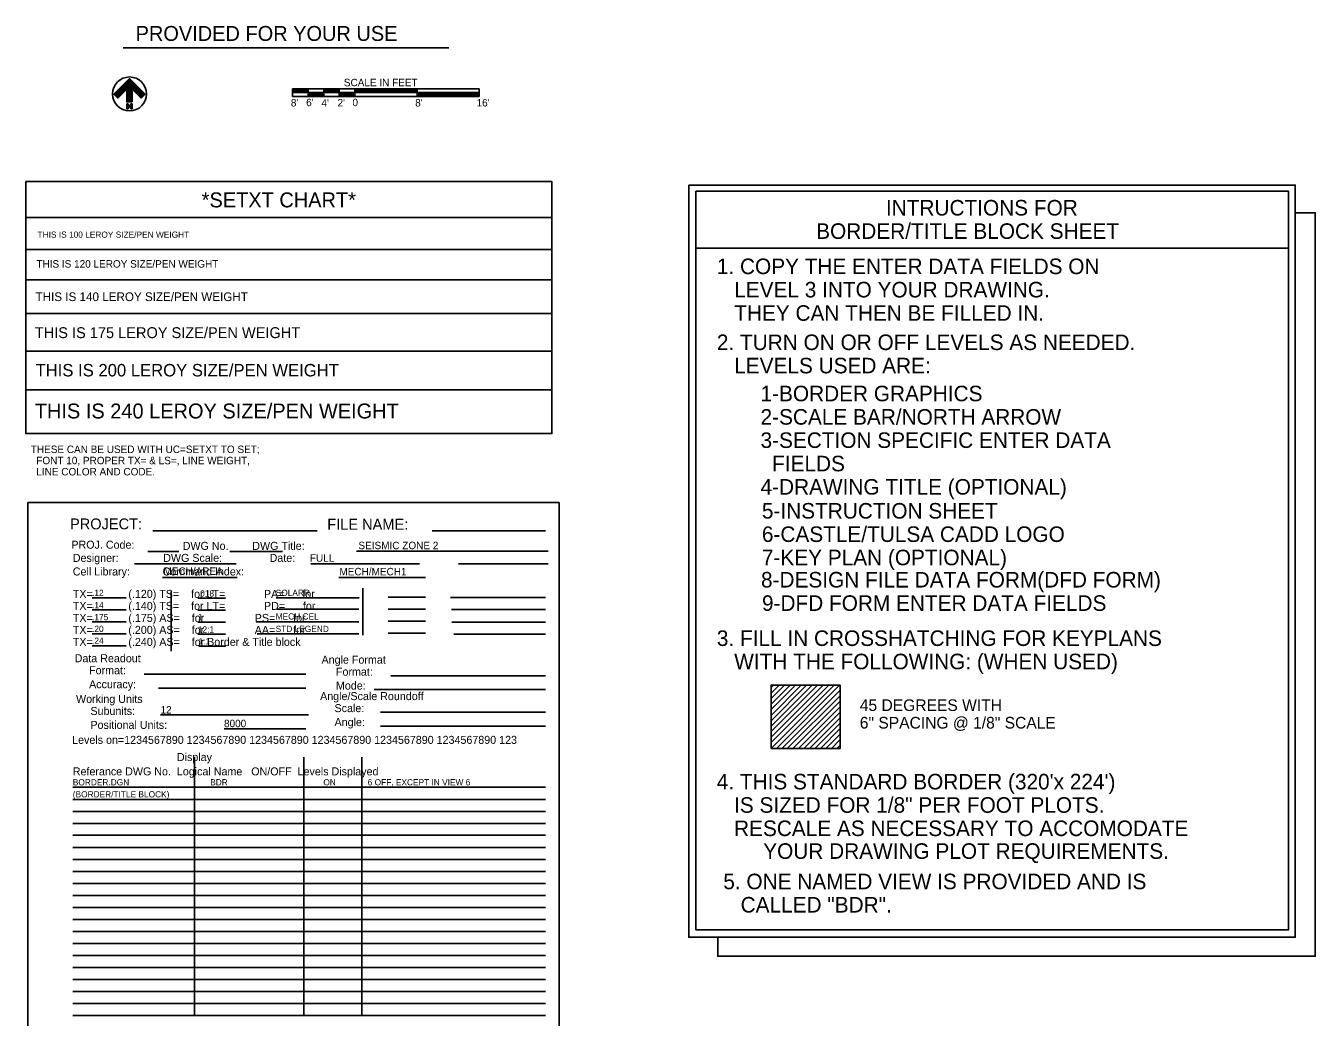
# Model space of a CAD drawing. Extents: x 9999.96 to 10005.26, y 9999.88 to 10002.38.
# Drawn here: x 10003.531 to 10005.258, y 10001.056 to 10002.384 of the extents above; entities that cross this region are included whole.
import ezdxf

# ---------------------------------------------------------------- set-up
doc = ezdxf.new("R2010")
doc.units = 0
for name, color, linetype in [('Level 2', 7, 'Continuous'), ('Level 5', 7, 'Continuous'), ('Level 8', 7, 'Continuous'), ('Level 9', 7, 'Continuous')]:
    doc.layers.add(name, color=color, linetype=linetype)

msp = doc.modelspace()

# ---------------------------------------------------------------- linework, layer by layer
at = {"layer": 'Level 2'}
for p, q in [((10003.6703, 10002.2818), (10003.6703, 10002.3131)), ((10003.8886, 10002.2995), (10004.1386, 10002.2995)), ((10003.8886, 10002.2995), (10003.8886, 10002.2891)), ((10003.8886, 10002.299), (10003.9095, 10002.299)), ((10003.8886, 10002.2981), (10003.9095, 10002.2981)), ((10003.8886, 10002.2973), (10003.9095, 10002.2973)), ((10003.8886, 10002.2964), (10003.9095, 10002.2964)), ((10003.8886, 10002.2955), (10003.9095, 10002.2955)), ((10003.8886, 10002.2947), (10003.9095, 10002.2947)), ((10003.9095, 10002.2995), (10003.9095, 10002.2891)), ((10003.9303, 10002.2995), (10003.9303, 10002.2891)), ((10003.9303, 10002.299), (10003.9511, 10002.299)), ((10003.9303, 10002.2981), (10003.9511, 10002.2981)), ((10003.9303, 10002.2972), (10003.9511, 10002.2972)), ((10003.9303, 10002.2964), (10003.9511, 10002.2964)), ((10003.9303, 10002.2955), (10003.9511, 10002.2955)), ((10003.9303, 10002.2946), (10003.9511, 10002.2946)), ((10003.9511, 10002.2995), (10003.9511, 10002.2891)), ((10003.9719, 10002.2989), (10004.0553, 10002.2989)), ((10003.9719, 10002.298), (10004.0553, 10002.298)), ((10003.9719, 10002.2971), (10004.0553, 10002.2971)), ((10003.9719, 10002.2963), (10004.0553, 10002.2963)), ((10003.9719, 10002.2954), (10004.0553, 10002.2954)), ((10003.972, 10002.2995), (10003.972, 10002.2891)), ((10004.0553, 10002.2995), (10004.0553, 10002.2891)), ((10004.1386, 10002.2995), (10004.1386, 10002.2891)), ((10003.6674, 10002.2726), (10003.6674, 10002.2792)), ((10003.6679, 10002.2726), (10003.6679, 10002.2792)), ((10003.6679, 10002.2788), (10003.6726, 10002.273)), ((10003.6726, 10002.2726), (10003.6726, 10002.2792)), ((10003.6731, 10002.2726), (10003.6731, 10002.2792)), ((10003.8886, 10002.2943), (10004.1386, 10002.2943)), ((10003.8886, 10002.2891), (10004.1386, 10002.2891)), ((10003.9094, 10002.2939), (10003.9303, 10002.2939)), ((10003.9094, 10002.293), (10003.9303, 10002.293)), ((10003.9094, 10002.2921), (10003.9303, 10002.2921)), ((10003.9094, 10002.2913), (10003.9303, 10002.2913)), ((10003.9094, 10002.2904), (10003.9303, 10002.2904)), ((10003.9094, 10002.2895), (10003.9303, 10002.2895)), ((10003.9511, 10002.2939), (10003.9719, 10002.2939)), ((10003.9511, 10002.293), (10003.9719, 10002.293)), ((10003.9511, 10002.2921), (10003.9719, 10002.2921)), ((10003.9511, 10002.2913), (10003.9719, 10002.2913)), ((10003.9511, 10002.2904), (10003.9719, 10002.2904)), ((10003.9511, 10002.2895), (10003.9719, 10002.2895)), ((10004.0553, 10002.2935), (10004.1386, 10002.2935)), ((10004.0553, 10002.2926), (10004.1386, 10002.2926)), ((10004.0553, 10002.2918), (10004.1386, 10002.2918)), ((10004.0553, 10002.2909), (10004.1386, 10002.2909)), ((10004.0553, 10002.29), (10004.1386, 10002.29))]:
    msp.add_line(p, q, dxfattribs=at)
for points in [[(10003.6739, 10002.2818), (10003.6739, 10002.299), (10003.6859, 10002.287), (10003.6911, 10002.2923), (10003.6703, 10002.3131), (10003.6494, 10002.2923), (10003.6546, 10002.287), (10003.6666, 10002.299), (10003.6666, 10002.2818)], [(10003.6668, 10002.2726), (10003.6668, 10002.2792), (10003.6682, 10002.2792), (10003.672, 10002.2744), (10003.672, 10002.2792), (10003.6737, 10002.2792), (10003.6737, 10002.2726), (10003.6723, 10002.2726), (10003.6685, 10002.2774), (10003.6685, 10002.2726)]]:
    msp.add_lwpolyline(points, close=True, dxfattribs=at)
for points in [[(10003.6501, 10002.2916), (10003.6703, 10002.3118), (10003.6904, 10002.2916)], [(10003.6507, 10002.291), (10003.6703, 10002.3105), (10003.6898, 10002.291)], [(10003.6514, 10002.2903), (10003.6703, 10002.3092), (10003.6891, 10002.2903)], [(10003.652, 10002.2897), (10003.6703, 10002.3079), (10003.6885, 10002.2897)], [(10003.6693, 10002.2818), (10003.6693, 10002.3057), (10003.6527, 10002.289)], [(10003.6684, 10002.2818), (10003.6684, 10002.3034), (10003.6533, 10002.2884)], [(10003.6675, 10002.2818), (10003.6675, 10002.3012), (10003.654, 10002.2877)], [(10003.6666, 10002.2818), (10003.6666, 10002.299), (10003.6546, 10002.287)], [(10003.6712, 10002.2818), (10003.6712, 10002.3057), (10003.6878, 10002.289)], [(10003.6721, 10002.2818), (10003.6721, 10002.3034), (10003.6872, 10002.2884)], [(10003.673, 10002.2818), (10003.673, 10002.3012), (10003.6865, 10002.2877)]]:
    msp.add_lwpolyline(points, dxfattribs=at)
msp.add_circle((10003.6703, 10002.2925), 0.0227, dxfattribs=at)
at = {"layer": 'Level 5'}
for p, q in [((10003.6616, 10002.3543), (10004.0978, 10002.3543)), ((10003.5313, 10002.127), (10004.2359, 10002.127)), ((10003.5313, 10002.0844), (10004.2359, 10002.0844)), ((10004.4285, 10002.0859), (10005.2225, 10002.0859)), ((10003.5313, 10002.0437), (10004.2359, 10002.0437)), ((10003.5313, 10001.9983), (10004.2359, 10001.9983)), ((10003.5313, 10001.9482), (10004.2359, 10001.9482)), ((10003.5313, 10001.8962), (10004.2359, 10001.8962)), ((10004.5291, 10001.4749), (10004.5549, 10001.5006)), ((10004.5291, 10001.4527), (10004.5769, 10001.5005)), ((10004.5291, 10001.4233), (10004.6063, 10001.5004)), ((10004.5291, 10001.4306), (10004.5989, 10001.5004)), ((10004.5292, 10001.4971), (10004.5328, 10001.5006)), ((10004.5292, 10001.4676), (10004.5622, 10001.5005)), ((10004.5292, 10001.4897), (10004.54, 10001.5005)), ((10004.5293, 10001.4161), (10004.6138, 10001.5006)), ((10004.5293, 10001.4603), (10004.5696, 10001.5006)), ((10004.5293, 10001.4456), (10004.5843, 10001.5005)), ((10004.5365, 10001.4159), (10004.6211, 10001.5006)), ((10004.5291, 10001.4822), (10004.5471, 10001.5002)), ((10004.5292, 10001.4381), (10004.5913, 10001.5002)), ((10004.5439, 10001.4159), (10004.622, 10001.4941)), ((10004.5516, 10001.4163), (10004.6219, 10001.4866)), ((10004.5588, 10001.4162), (10004.6219, 10001.4793)), ((10004.5661, 10001.4161), (10004.6218, 10001.4718)), ((10004.5734, 10001.4161), (10004.6219, 10001.4645)), ((10004.5808, 10001.416), (10004.6218, 10001.4571)), ((10004.5881, 10001.416), (10004.6221, 10001.45)), ((10004.5955, 10001.416), (10004.6219, 10001.4425)), ((10004.6027, 10001.4158), (10004.6221, 10001.4352)), ((10004.6103, 10001.4161), (10004.6221, 10001.4278)), ((10004.6176, 10001.4161), (10004.6221, 10001.4205))]:
    msp.add_line(p, q, dxfattribs=at)
for points in [[(10003.5313, 10002.1752), (10004.2359, 10002.1752), (10004.2359, 10001.8376), (10003.5313, 10001.8376), (10003.5313, 10002.1752)], [(10004.4192, 10002.1705), (10005.2314, 10002.1705), (10005.2314, 10001.1631), (10004.4192, 10001.1631), (10004.4192, 10002.1705)], [(10004.4285, 10002.1621), (10005.2225, 10002.1621), (10005.2225, 10001.1732), (10004.4285, 10001.1732), (10004.4285, 10002.1621)], [(10005.2314, 10002.1335), (10005.2581, 10002.1335), (10005.2581, 10001.1376), (10004.4579, 10001.1376), (10004.4579, 10001.1631)]]:
    msp.add_lwpolyline(points, dxfattribs=at)
msp.add_lwpolyline([(10004.5293, 10001.4161), (10004.5293, 10001.5006), (10004.6221, 10001.5006), (10004.6221, 10001.4161)], close=True, dxfattribs=at)
at = {"layer": 'Level 8'}
for p, q in [((10003.5343, 9999.912), (10003.5343, 10001.7453)), ((10003.5343, 10001.7453), (10004.2454, 10001.7453)), ((10004.2454, 10001.7453), (10004.2454, 9999.912)), ((10003.9217, 10001.7073), (10003.7016, 10001.7073)), ((10004.2274, 10001.7073), (10004.0755, 10001.7073)), ((10003.7361, 10001.6795), (10003.6947, 10001.6795)), ((10003.8753, 10001.6795), (10003.8045, 10001.6795)), ((10004.231, 10001.6801), (10003.9744, 10001.6801)), ((10003.6768, 10001.6632), (10003.8132, 10001.6632)), ((10003.9129, 10001.6632), (10004.0588, 10001.6632)), ((10004.1108, 10001.6632), (10004.231, 10001.6632)), ((10003.7145, 10001.645), (10003.8143, 10001.645)), ((10003.9507, 10001.645), (10004.0665, 10001.645)), ((10003.7261, 10001.6262), (10003.7261, 10001.5464)), ((10003.9829, 10001.5676), (10003.9829, 10001.6304)), ((10003.6658, 10001.6176), (10003.6204, 10001.6176)), ((10003.7989, 10001.6171), (10003.7619, 10001.6171)), ((10003.9778, 10001.6178), (10003.8665, 10001.6178)), ((10004.0665, 10001.6185), (10004.0167, 10001.6185)), ((10004.2274, 10001.6179), (10004.1003, 10001.6179)), ((10003.6658, 10001.6015), (10003.6204, 10001.6015)), ((10003.7989, 10001.6011), (10003.7619, 10001.6011)), ((10003.9772, 10001.6023), (10003.8676, 10001.6023)), ((10004.0665, 10001.6024), (10004.0167, 10001.6024)), ((10004.2274, 10001.6019), (10004.1014, 10001.6019)), ((10003.6658, 10001.5854), (10003.6204, 10001.5854)), ((10003.7989, 10001.585), (10003.7619, 10001.585)), ((10003.9772, 10001.5857), (10003.84, 10001.5857)), ((10003.9772, 10001.5696), (10003.841, 10001.5696)), ((10004.0665, 10001.5863), (10004.0167, 10001.5863)), ((10004.0665, 10001.5703), (10004.0167, 10001.5703)), ((10004.2274, 10001.5853), (10004.1019, 10001.5853)), ((10003.6658, 10001.5694), (10003.6204, 10001.5694)), ((10003.6658, 10001.5533), (10003.6204, 10001.5533)), ((10003.7989, 10001.5689), (10003.7619, 10001.5689)), ((10003.7989, 10001.5528), (10003.763, 10001.5528)), ((10004.2274, 10001.5692), (10004.1047, 10001.5692)), ((10003.9064, 10001.5153), (10003.6897, 10001.5153)), ((10004.02, 10001.5134), (10004.2274, 10001.5134)), ((10003.9064, 10001.4966), (10003.7092, 10001.4966)), ((10004.2274, 10001.4948), (10003.9979, 10001.4948)), ((10003.91, 10001.4608), (10003.7118, 10001.4608)), ((10004.2274, 10001.4646), (10004.0063, 10001.4646)), ((10003.9064, 10001.4422), (10003.797, 10001.4422)), ((10004.2274, 10001.4459), (10004.0063, 10001.4459)), ((10003.7574, 10001.4044), (10003.7574, 10001.0584)), ((10003.9037, 10001.4044), (10003.9037, 10001.0595)), ((10003.9814, 10001.4044), (10003.9814, 10001.0584)), ((10004.2274, 10001.3639), (10003.5943, 10001.3639)), ((10004.2274, 10001.3478), (10003.5943, 10001.3478)), ((10004.2274, 10001.3317), (10003.5943, 10001.3317)), ((10004.2274, 10001.3156), (10003.5943, 10001.3156)), ((10004.2274, 10001.2996), (10003.5943, 10001.2996)), ((10004.2274, 10001.2835), (10003.5943, 10001.2835)), ((10004.2274, 10001.2674), (10003.5943, 10001.2674)), ((10004.2274, 10001.2513), (10003.5943, 10001.2513)), ((10004.2274, 10001.2352), (10003.5943, 10001.2352)), ((10004.2274, 10001.2192), (10003.5943, 10001.2192)), ((10004.2274, 10001.2031), (10003.5943, 10001.2031)), ((10004.2274, 10001.187), (10003.5943, 10001.187)), ((10004.2274, 10001.1709), (10003.5943, 10001.1709)), ((10004.2274, 10001.1549), (10003.5943, 10001.1549)), ((10004.2274, 10001.1388), (10003.5943, 10001.1388)), ((10004.2274, 10001.1227), (10003.5943, 10001.1227)), ((10004.2274, 10001.1066), (10003.5943, 10001.1066)), ((10004.2274, 10001.0906), (10003.5943, 10001.0906)), ((10004.2274, 10001.0745), (10003.5943, 10001.0745)), ((10004.2274, 10001.0584), (10003.5943, 10001.0584))]:
    msp.add_line(p, q, dxfattribs=at)

# ---------------------------------------------------------------- texts
at = {"layer": 'Level 2'}
for s, p in [('SCALE IN FEET', (10003.9573, 10002.3028)), ("8'", (10003.8863, 10002.2757)), ("6'", (10003.9068, 10002.2761)), ("4'", (10003.9272, 10002.2754)), ("2'", (10003.9488, 10002.2757)), ('0', (10003.9688, 10002.2761)), ("8'", (10004.0528, 10002.2757)), ("16'", (10004.135, 10002.2757))]:
    msp.add_text(s, height=0.01, dxfattribs=at).set_placement(p)
at = {"layer": 'Level 5'}
for s, height, p in [('PROVIDED FOR YOUR USE', 0.02, (10003.6784, 10002.3635)), ('*SETXT CHART*', 0.02, (10003.7669, 10002.1406)), ('INTRUCTIONS FOR', 0.020833, (10004.6832, 10002.1297)), ('THIS IS 100 LEROY SIZE/PEN WEIGHT', 0.008333, (10003.5471, 10002.0999)), ('BORDER/TITLE BLOCK SHEET', 0.020833, (10004.5898, 10002.0984)), ('THIS IS 120 LEROY SIZE/PEN WEIGHT', 0.01, (10003.5455, 10002.0599)), ('1. COPY THE ENTER DATA FIELDS ON', 0.020833, (10004.4568, 10002.0512)), ('   LEVEL 3 INTO YOUR DRAWING.', 0.020833, (10004.4568, 10002.02)), ('THIS IS 140 LEROY SIZE/PEN WEIGHT', 0.011667, (10003.5444, 10002.0151)), ('   THEY CAN THEN BE FILLED IN.', 0.020833, (10004.4568, 10001.9887)), ('THIS IS 175 LEROY SIZE/PEN WEIGHT', 0.014583, (10003.5434, 10001.9655)), ('2. TURN ON OR OFF LEVELS AS NEEDED.', 0.020833, (10004.4568, 10001.9495)), ('   LEVELS USED ARE:', 0.020833, (10004.4568, 10001.9183)), ('THIS IS 200 LEROY SIZE/PEN WEIGHT', 0.016667, (10003.5444, 10001.9142)), ('1-BORDER GRAPHICS', 0.020833, (10004.5153, 10001.8809)), ('THIS IS 240 LEROY SIZE/PEN WEIGHT', 0.02, (10003.5434, 10001.8579)), ('2-SCALE BAR/NORTH ARROW', 0.020833, (10004.5153, 10001.8496)), ('3-SECTION SPECIFIC ENTER DATA', 0.020833, (10004.5153, 10001.8184)), ('THESE CAN BE USED WITH UC=SETXT TO SET;', 0.01, (10003.538, 10001.8116)), ('  FONT 10, PROPER TX= & LS=, LINE WEIGHT,', 0.01, (10003.538, 10001.7966)), ('  FIELDS', 0.02083, (10004.5153, 10001.7871)), ('  LINE COLOR AND CODE.', 0.01, (10003.538, 10001.7816)), ('4-DRAWING TITLE (OPTIONAL)', 0.020833, (10004.5153, 10001.7559)), ('5-INSTRUCTION SHEET', 0.020833, (10004.5171, 10001.7238)), ('6-CASTLE/TULSA CADD LOGO', 0.020833, (10004.5171, 10001.6925)), ('7-KEY PLAN (OPTIONAL)', 0.020833, (10004.5171, 10001.6613)), ('8-DESIGN FILE DATA FORM(DFD FORM)', 0.020833, (10004.5159, 10001.6315)), ('9-DFD FORM ENTER DATA FIELDS', 0.020833, (10004.5172, 10001.6002)), ('3. FILL IN CROSSHATCHING FOR KEYPLANS', 0.020833, (10004.4568, 10001.5532)), ('   WITH THE FOLLOWING: (WHEN USED)', 0.020833, (10004.4568, 10001.522)), ('45 DEGREES WITH', 0.015625, (10004.6482, 10001.4661)), ('6" SPACING @ 1/8" SCALE', 0.015625, (10004.6482, 10001.4426)), ("4. THIS STANDARD BORDER (320'x 224')", 0.020833, (10004.4566, 10001.3611)), ('   IS SIZED FOR 1/8" PER FOOT PLOTS.', 0.020833, (10004.4566, 10001.3298)), ('   RESCALE AS NECESSARY TO ACCOMODATE', 0.020833, (10004.4566, 10001.2986)), ('YOUR DRAWING PLOT REQUIREMENTS.', 0.020833, (10004.5189, 10001.2681)), ('5. ONE NAMED VIEW IS PROVIDED AND IS', 0.020833, (10004.4654, 10001.2274)), ('   CALLED "BDR".', 0.020833, (10004.4654, 10001.1962))]:
    msp.add_text(s, height=height, dxfattribs=at).set_placement(p)
at = {"layer": 'Level 8'}
for s, height, p in [('PROJECT:', 0.01459, (10003.5906, 10001.7094)), ('FILE NAME:', 0.01459, (10003.9351, 10001.7089)), ('PROJ. Code:', 0.010717, (10003.5924, 10001.6835)), ('DWG No.        DWG Title:', 0.010717, (10003.7415, 10001.6819)), ('Designer:               DWG Scale:                Date:', 0.010717, (10003.5943, 10001.6658)), ('Cell Library:           Command Index:', 0.010717, (10003.5943, 10001.6476)), ('TX=', 0.01072, (10003.5943, 10001.6176)), ('(.120) TS=    for LT=             PA=      for', 0.010717, (10003.6687, 10001.6176)), ('TX=', 0.01072, (10003.5943, 10001.6015)), ('(.140) TS=    for LT=             PD=      for', 0.010717, (10003.6687, 10001.6015)), ('TX=', 0.01072, (10003.5943, 10001.5854)), ('(.175) AS=    for                 PS=      for', 0.010717, (10003.6687, 10001.5854)), ('TX=', 0.01072, (10003.5943, 10001.5694)), ('(.200) AS=    for                 AA=      for', 0.010717, (10003.6687, 10001.5694)), ('TX=', 0.01072, (10003.5943, 10001.5533)), ('(.240) AS=    for Border & Title block', 0.010717, (10003.6687, 10001.5533)), ('Data Readout', 0.010717, (10003.5968, 10001.5314)), ('Angle Format', 0.010717, (10003.9274, 10001.5295)), ('Format:', 0.01072, (10003.6161, 10001.5153)), ('Format:', 0.01072, (10003.9467, 10001.5134)), ('Accuracy:', 0.01072, (10003.6161, 10001.4966)), ('Mode:', 0.01072, (10003.9467, 10001.4948)), ('Working Units', 0.010717, (10003.5986, 10001.4769)), ('Angle/Scale Roundoff', 0.010717, (10003.9255, 10001.4807)), ('Subunits:', 0.01072, (10003.6179, 10001.4608)), ('Scale:', 0.01072, (10003.9448, 10001.4646)), ('Positional Units:', 0.010717, (10003.6179, 10001.4422)), ('Angle:', 0.01072, (10003.9448, 10001.4459)), ('Levels on=1234567890 1234567890 1234567890 1234567890 1234567890 1234567890 123', 0.010717, (10003.5934, 10001.4221)), ('                                 Display ', 0.010717, (10003.6023, 10001.3991)), ('Referance DWG No.  Logical Name   ON/OFF  Levels Displayed', 0.010717, (10003.5943, 10001.3799))]:
    msp.add_text(s, height=height, dxfattribs=at).set_placement(p)
at = {"layer": 'Level 9'}
for s, height, p in [('SEISMIC ZONE 2            ', 0.010001, (10003.9768, 10001.6828)), ('FULL          ', 0.010001, (10003.9118, 10001.6661)), ('MECH/AREA', 0.01, (10003.7157, 10001.6484)), ('MECH/MECH1 ', 0.01, (10003.9513, 10001.6478)), ('.12 ', 0.00833, (10003.6201, 10001.6202)), ('.018', 0.00833, (10003.7618, 10001.6194)), ('SOLARR      ', 0.008331, (10003.866, 10001.6202)), ('.14 ', 0.00833, (10003.6201, 10001.6036)), ('.175', 0.00833, (10003.6201, 10001.5877)), ('1   ', 0.00833, (10003.7618, 10001.5877)), ('MECH.CEL    ', 0.008331, (10003.866, 10001.5886)), ('.20 ', 0.00833, (10003.6201, 10001.5719)), ('12:1', 0.00833, (10003.7618, 10001.5711)), ('STD LEGEND  ', 0.008331, (10003.866, 10001.5719)), ('.24 ', 0.00833, (10003.6201, 10001.5561)), ('1:1 ', 0.00833, (10003.7626, 10001.5552)), ('12                  ', 0.010001, (10003.7118, 10001.4627)), ('8000     ', 0.01, (10003.7968, 10001.4444)), ('BORDER.DGN          ', 0.008333, (10003.5943, 10001.3665)), ('BDR       ', 0.00833, (10003.7783, 10001.3665)), ('ON ', 0.00833, (10003.9298, 10001.3665)), ('6 OFF, EXCEPT IN VIEW 6       ', 0.008333, (10003.9892, 10001.3665)), ('(BORDER/TITLE BLOCK)', 0.008333, (10003.5943, 10001.3504))]:
    msp.add_text(s, height=height, dxfattribs=at).set_placement(p)

doc.saveas('drawing.dxf')
